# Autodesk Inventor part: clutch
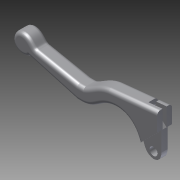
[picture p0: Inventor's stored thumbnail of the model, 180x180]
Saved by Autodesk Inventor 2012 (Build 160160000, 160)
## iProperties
Created: 2012-05
Part Number: clutch
Material: Default
Document SubType Name: Modeling
Designer: Will
Density: 1 g/cm^3
Author: Will
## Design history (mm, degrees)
sketch "Sketch1"
  geometry: L1 (0, 0)-(0, -35.105); L2 (-75.129, -15.533)-(-113.381, -7.935); L3 (-75.129, -28.371)-(-120.193, -15.533); L4 (0, 0)-(-46.048, -4.791); L5 (0, -16.966)-(-16.929, -34.115); L6 (-106.942, -10.434)-(-119.819, -5.436); L7 (-113.88, -8.48)-(-117.504, -5.198); L8 (-8.752, -44.069)-(-5.999, -43.815); C1 r 3.746 at (-7.375, -37.782); A1 r 21.989 centre (-121.336, -28.434) between (-108.625, -10.492) and (-118.616, -6.614); A2 r 5.623 centre (-111.917, -2.672) between (-116.852, -5.368) and (-114.114, -7.848); A3 r 14.21 centre (-8.682, -29.792) between (-8.477, -44.001) and (-6.281, -43.798); 17 further points
  constraints: 16 end point, 6 midpoint, 4 centre point, 3 point on circle, 2 point on line, 1 vertical, 33 other
  dimensions: "d1" = 7.493 diameter of C1; "d2" = 37.78244 vertical distance of L1.start C1.centre
extrude "Extrusion1" new body sketch "Sketch1" stored distance "d3" = 14.097; taper "d4" = 0 deg
sketch "Sketch2"
  geometry: L1 (0, 0)-(0, -35.105); L2 (0, -16.966)-(-16.929, -34.115); L3 (-8.752, -44.069)-(-5.999, -43.815); C1 r 3.746 at (-7.375, -37.782); A1 r 14.21 centre (-8.682, -29.792) between (-8.477, -44.001) and (-6.281, -43.798); 11 further points
  constraints: 6 end point, 2 centre point, 2 midpoint, 2 point on line, 1 point on circle, 1 vertical, 16 other
  dimensions: "d5" = 7.493 diameter of C1; "d6" = 37.78244 vertical distance of L1.start C1.centre
extrude "Extrusion2" join sketch "Sketch2" stored distance "d7" = 5.842; taper "d8" = 0 deg
sketch "Sketch3"
  geometry: L1 (0, 16.966)-(14.097, 16.966) reference; L2 (8.954, 16.966)-(5.144, 16.966); L3 (5.144, 16.966)-(5.144, 5.967); L4 (5.144, 5.967)-(8.954, 5.967); L5 (8.954, 5.967)-(8.954, 16.966); 1 further point
  constraints: 8 end point, 2 parallel, 1 horizontal, 1 perpendicular, 1 point on line
  dimensions: "d9" = 10.9982 distance of L4.end L2.start; "d10" = 3.81 distance of L3.end L4.end; "d11" = 1.905 distance from line of point (7.049, 16.966) L5
extrude "Extrusion3" cut sketch "Sketch3" distance "d12" = 13.208; taper "d13" = 0 deg
sketch "Sketch4"
  geometry: L1 (0, 0)-(46.048, -4.791) reference; L2 (0, -16.966)-(0, 0) reference; C1 r 4.318 at (10.922, -9.691)
  constraints: 1 centre point
  dimensions: "d14" = 8.636 diameter of C1; "d15" = 10.922 distance from line of L2 C1.centre; "d16" = 8.509 distance from line of L1 C1.centre
extrude "Extrusion4" cut sketch "Sketch4" distance "d17" = 11.303; taper "d18" = 0 deg
sketch "Sketch5"
  geometry: L1 (0, -10.998)-(-6.807, -10.998) reference; L2 (0, 0)-(0, -16.966) reference; L3 (-6.807, -10.998)-(0, -10.998); L4 (0, -16.966)-(-6.807, -10.998); L5 (0, -10.998)-(0, -16.966)
  constraints: 6 end point, 2 collinear
extrude "Extrusion5" cut sketch "Sketch5" stored distance "d19" = 3.81; taper "d20" = 0 deg
fillet "Fillet1" dims "d21" = 3.429
sketch "Sketch6"
  geometry: L1 (121.158, -11.692)-(74.687, -24.931) reference; L2 (13.208, -6.028)-(13.208, -1.374) reference; L3 (13.208, -1.374)-(13.208, -6.028) reference; L4 (13.208, -6.028)-(13.208, 0.365); L5 (13.208, 0.365)-(9.398, 0.365); L6 (9.398, 0.365)-(11.033, -5.375); A1 r 4.318 centre (10.922, -9.691) between (13.208, -6.028) and (11.033, -5.375); 2 further points
  constraints: 6 end point, 2 perpendicular, 2 point on circle, 1 centre point, 1 point on line, 3 other
  dimensions: "d22" = 3.81 distance of L4.end L5.end
extrude "Extrusion6" cut sketch "Sketch6" distance "d23" = 5.1562; taper "d24" = 0 deg
body "Solid1"
node "Projected Loop1"
